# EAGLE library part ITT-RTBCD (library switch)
ROTARY SWITCH ITT-Cannon
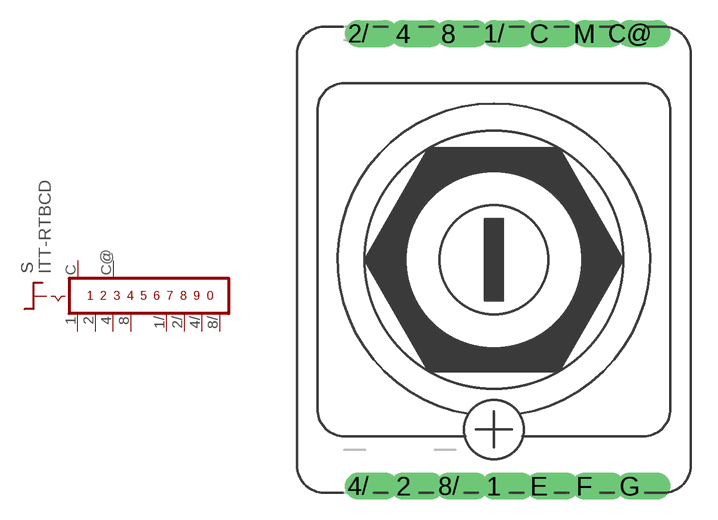
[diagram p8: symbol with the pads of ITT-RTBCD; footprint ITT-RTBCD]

Designator prefix S

## ITT-RTBCD  [ITT-RTBCD]
1  1  pas
1/  1/  pas
2  2  pas
2/  2/  pas
4  4  pas
4/  4/  pas
8  8  pas
8/  8/  pas
C  C  pas
C@  C  pas

## Footprint ITT-RTBCD (pad centres in mm)
ROTARY SWITCH ITT-Cannon
drill 1.016 offset: 1 0,-12.7; 1/ 0,12.7; 2 -5.08,-12.7; 2/ -7.62,12.7; 4 -5.08,12.7; 4/ -7.62,-12.7; 8 -2.54,12.7; 8/ -2.54,-12.7; C 2.54,12.7; C@ 7.62,12.7; E 2.54,-12.7; F 5.08,-12.7; G 7.62,-12.7; M 5.08,12.7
